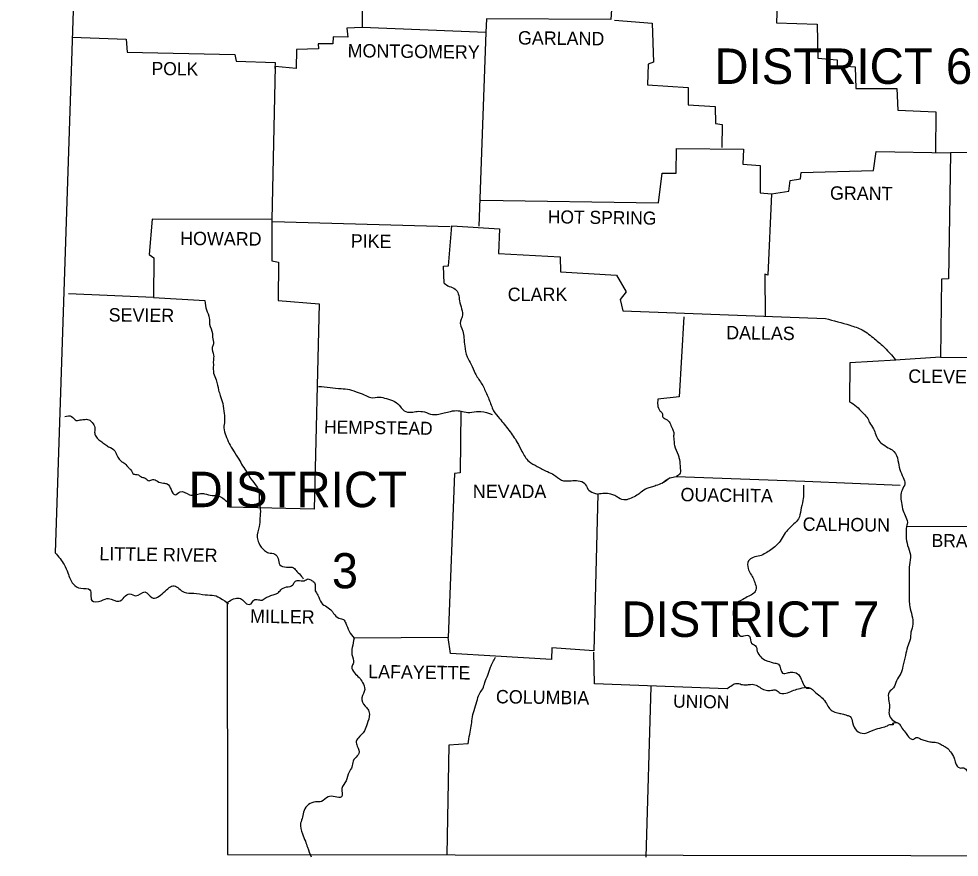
# Model space of a CAD drawing. Extents: x -17668 to 16999, y -17303 to 5867.
# Drawn here: x 1332 to 2998, y 2895 to 4379 of the extents above; entities that cross this region are included whole.
import ezdxf

# ---------------------------------------------------------------- set-up
doc = ezdxf.new("R2010")
doc.units = 0
for name, color, linetype in [('1', 7, 'Continuous'), ('2', 7, 'Continuous'), ('3', 7, 'Continuous')]:
    doc.layers.add(name, color=color, linetype=linetype)

msp = doc.modelspace()

# ---------------------------------------------------------------- linework, layer by layer
at = {"layer": '1'}
for points in [[(1332.2, 5841.4), (1446.1, 4926.7), (1396.6, 3433.6)], [(1941.4, 4685.1), (1940.3, 4363.2), (1912.8, 4362.6), (1915, 4346.1), (1888.6, 4346.7), (1888, 4334.6), (1862.2, 4334.6), (1862.7, 4325.8), (1824.2, 4324.7), (1823.6, 4291.1), (1786.2, 4294.4), (1780.2, 4023.6), (1568.3, 4024.2), (1563.3, 3961.4), (1571, 3955.9), (1570.5, 3885.5), (1420.2, 3892.1)], [(2565.5, 4443), (2385.5, 4448.5), (2380.6, 4377.5), (2160.4, 4378.6), (2159.3, 4354.9)], [(2614.5, 4444.6), (2676.1, 4440.8), (2673.9, 4372), (2746, 4369.2), (2747.1, 4309.2), (2781.2, 4306.5), (2781.2, 4296), (2813.2, 4293.8), (2814.3, 4255.3), (2886.9, 4255.3), (2889.1, 4217.3), (2956.3, 4214), (2955.7, 4142.5)], [(2387.2, 4376.4), (2453.8, 4371.4), (2456, 4302.1), (2446.6, 4298.8), (2445.5, 4261.9), (2517.6, 4257), (2517.6, 4226.7), (2565.5, 4223.9), (2566.1, 4193.7), (2577.6, 4192), (2577.1, 4151.3)], [(2159.3, 4354.9), (1940.3, 4363.2)], [(2159.3, 4354.9), (2146.7, 4012.1)], [(1426.8, 4346.1), (1522, 4342.8), (1524.2, 4319.7), (1714.7, 4315.8), (1716.9, 4303.7), (1786.2, 4301.5), (1785.7, 4291.1)], [(3612.3, 4205.8), (3404.2, 4211.3), (3403.1, 4143.6), (2982.1, 4141.9)], [(2150.5, 4057.7), (2465.3, 4053.3), (2471.4, 4105.6), (2496.2, 4105.6), (2496.7, 4149.6), (2615.6, 4148), (2614.5, 4121.6), (2645.3, 4119.4), (2645.3, 4070.9), (2665.1, 4069.3)], [(2665.1, 4069.3), (2695.9, 4073.7), (2698.1, 4092.4), (2716.3, 4095.7), (2717.4, 4106.7), (2845.6, 4110.6), (2850.6, 4144.1), (2982.1, 4141.9)], [(2982.1, 4140.8), (2978.8, 3918.5), (2966.2, 3917.9), (2964.5, 3779.8)], [(2665.1, 4069.3), (2658.5, 3925.1), (2653.6, 3926.7), (2654.1, 3851.9)], [(1780.2, 4023.6), (1780.2, 3950.4), (1792.3, 3948.2), (1791.2, 3880), (1863.8, 3874.5), (1855, 3510.7), (1705.3, 3514.5)], [(1781.3, 4019.8), (2096.1, 4011.5)], [(2085.6, 3910.8), (2084.5, 3941.1), (2093.3, 3941.6), (2098.8, 4012.6), (2183.6, 4007.1), (2181.4, 3963.6), (2290.9, 3957.6), (2291.4, 3931.2), (2390.5, 3925.1), (2407.6, 3895.4), (2397.1, 3882.2), (2402.1, 3861.8), (2760.9, 3848.6)], [(1570.5, 3885.5), (1661.8, 3880)], [(2509.9, 3851.4), (2501.7, 3709.9), (2463.7, 3705.5)], [(2885.3, 3774.9), (2803.8, 3769.9), (2803.3, 3701.1)], [(2964.5, 3779.8), (2884.2, 3774.9)], [(2964.5, 3779.8), (3159.3, 3778.7)], [(2114.8, 3684.6), (2113.7, 3575.1), (2103.8, 3574), (2092.8, 3283.9)], [(2496.2, 3568.5), (2724, 3560.2), (2893, 3553.6)], [(2357.5, 3537.6), (2350.3, 3260.3), (2276, 3265.2), (2275.5, 3244.9), (2176.4, 3250.9)], [(2904, 3480.4), (3152.7, 3481)], [(1700.9, 3345), (1702, 2899.8), (3719, 2896.5)], [(2176.4, 3250.9), (2096.6, 3255.3), (2092.8, 3283.9), (1926, 3282.3)], [(2586.4, 3193.1), (2351.4, 3201.9), (2350.3, 3257.5)], [(2451.6, 3197), (2442.8, 2894.8)], [(2128, 3095.2), (2093.9, 3093), (2090, 2899.2)]]:
    msp.add_lwpolyline(points, dxfattribs=at)
for points in [[(2085.6, 3910.8), (2094.4, 3905.3), (2104.9, 3900.3), (2110.4, 3892.1), (2112.6, 3879.4), (2116.4, 3865.7), (2117.5, 3851.4), (2114.2, 3843.6), (2118.6, 3826), (2120.3, 3813.9), (2121.9, 3799.6), (2126.3, 3780.4), (2133.5, 3767.1), (2140.1, 3751.2), (2151.1, 3734.1), (2160.4, 3715.4), (2164.8, 3705.5), (2173.1, 3685.1), (2183.6, 3671.4), (2200.1, 3650.5), (2214.9, 3629), (2223.2, 3613), (2235.8, 3595.4), (2250.2, 3586.6), (2268.3, 3577.3), (2279.9, 3571.8), (2293.1, 3562.4), (2310.1, 3561.3), (2322.8, 3561.3), (2334.4, 3556.4), (2339.9, 3546.5), (2349.8, 3539.9), (2357.5, 3537.6)], [(1661.8, 3880), (1664.6, 3863.5), (1669.5, 3849.1), (1670.1, 3838.1), (1675, 3821.6), (1675, 3815.6), (1676.7, 3803.5), (1674.5, 3796.9), (1677.2, 3783.7), (1676.7, 3773.8), (1676.7, 3765.5), (1677.2, 3751.7), (1681.6, 3739.6), (1686, 3721.5), (1688.8, 3712.1), (1693.2, 3697.8), (1695.9, 3680.2), (1696.5, 3667), (1695.4, 3654.9), (1698.7, 3641.1), (1704.8, 3627.4), (1712.5, 3614.1), (1721.8, 3599.3), (1728.4, 3587.7), (1736.7, 3575.1), (1743.3, 3564.6), (1753.2, 3551.4), (1757.6, 3540.4), (1757.6, 3525), (1759.8, 3510.7), (1759.2, 3494.7), (1758.1, 3480.4), (1754.3, 3460.6), (1757, 3451.2), (1767.5, 3437.5), (1774.1, 3433.6), (1785.7, 3431.4), (1791.2, 3423.7), (1794.5, 3412.2), (1806, 3408.3), (1818.7, 3407.2), (1824.7, 3400.6), (1833, 3391.8), (1835.7, 3387.4)], [(2760.9, 3848.6), (2803.8, 3836.5), (2825.8, 3828.2), (2847.8, 3812.3), (2866, 3796.3), (2884.2, 3776)], [(1862.7, 3728.1), (1883.6, 3726.4), (1902.9, 3724.2), (1917.7, 3722.6), (1933.2, 3717.1), (1946.9, 3712.1), (1955.7, 3708.3), (1970.6, 3709.4), (1983.2, 3706.6), (1997.5, 3701.7), (2008, 3692.3), (2014.6, 3685.1), (2027.3, 3682.4), (2037.7, 3684), (2050.4, 3682.9), (2064.7, 3678.5), (2076.2, 3679.1), (2085.6, 3681.3), (2096.6, 3684), (2110.4, 3685.1), (2120.8, 3682.9), (2134.6, 3682.4), (2150.5, 3684), (2170.4, 3678.5)], [(2463.7, 3705.5), (2463.7, 3695), (2467.5, 3685.1), (2471.4, 3680.7), (2473, 3673.6), (2478, 3670.3), (2485.2, 3663.7), (2489, 3654.3), (2491.8, 3648.3), (2491.8, 3640.6), (2492.3, 3632.9), (2493.4, 3623.5), (2500, 3607), (2501.7, 3600.4), (2502.8, 3594.9), (2503.3, 3585.5), (2503.3, 3574.5), (2496.2, 3568.5)], [(2803.3, 3701.1), (2815.9, 3692.8), (2826.4, 3681.8), (2834.1, 3673.6), (2839, 3664.2), (2845.6, 3653.2), (2855, 3632.3), (2863.2, 3625.2), (2874.8, 3618), (2882, 3613), (2889.1, 3597.1), (2892.4, 3581.1), (2898.5, 3566.8), (2901.2, 3555.8), (2896.3, 3544.8), (2895.2, 3522.8), (2898.5, 3507.9), (2902.9, 3496.9), (2905.6, 3484.3), (2904, 3480.4)], [(1413.6, 3674.7), (1425.7, 3675.2), (1434, 3668.1), (1438.9, 3668.6), (1447.7, 3669.7), (1456, 3669.2), (1462, 3664.2), (1467, 3655.4), (1466.5, 3647.2), (1467, 3643.9), (1470.9, 3636.7), (1477.5, 3631.2), (1484.6, 3625.7), (1491.2, 3621.3), (1502.2, 3614.1), (1503.3, 3611.9), (1507.7, 3603.1), (1513.2, 3596), (1519.8, 3591.6), (1527, 3583.9), (1530.3, 3580.6), (1535.8, 3572.9), (1541.8, 3572.3), (1550.1, 3567.4), (1556.2, 3565.7), (1562.8, 3561.3), (1569.4, 3563.5), (1577.6, 3560.2), (1588.6, 3556.9), (1594.7, 3555.8), (1601.8, 3545.4), (1609, 3536.5), (1617.8, 3541.5), (1634.3, 3536.5), (1644.8, 3536), (1654.1, 3538.7), (1661.3, 3538.2), (1674.5, 3534.9), (1682.7, 3534.9), (1691.5, 3531.6), (1699.8, 3525), (1705.3, 3517.8), (1705.3, 3514.5)], [(2485.7, 3566.3), (2471.4, 3556.9), (2460.4, 3552.5), (2452.1, 3549.8), (2444.4, 3547.6), (2434.5, 3541), (2426.8, 3535.4), (2416.4, 3530.5), (2406.5, 3527.2), (2394.3, 3531), (2387.7, 3534.9), (2380.6, 3537.6), (2357.5, 3537.6)], [(2471.4, 3556.9), (2485.7, 3566.3), (2496.2, 3568.5)], [(2721.8, 3553.6), (2720.7, 3526.1), (2716.9, 3509), (2713, 3493.6), (2704.7, 3484.8), (2695.9, 3476), (2687.7, 3466.1), (2680.5, 3454), (2673.4, 3446.3), (2664, 3438.6), (2654.7, 3433.1), (2644.2, 3428.1), (2632.7, 3425.4), (2624.4, 3419.3), (2623.8, 3406.1), (2633.2, 3387.4), (2636.5, 3378.6), (2637.6, 3368.1), (2633.8, 3362.1), (2624.9, 3357.1), (2614.5, 3351.1), (2605.1, 3345.6), (2598.5, 3336.2), (2597.4, 3323.6), (2601.8, 3308.7), (2603.5, 3299.9), (2610.6, 3286.1), (2616.1, 3286.7), (2626, 3286.1), (2627.1, 3283.4), (2627.7, 3280.6), (2629.9, 3273.5), (2638.2, 3267.4), (2639.3, 3261.9), (2644.2, 3251.5), (2652.5, 3244.3), (2658.5, 3242.1), (2671.2, 3238.3), (2677.8, 3236.6), (2684.9, 3220.6), (2693.7, 3221.2), (2700.3, 3222.3), (2711.4, 3219.5), (2716.3, 3212.9), (2721.3, 3201.9), (2727.9, 3194.2), (2732.3, 3194.2)], [(2904, 3480.4), (2906.2, 3446.3), (2911.1, 3429.8), (2909.5, 3412.2), (2908.9, 3395.1), (2908.9, 3379.7), (2908.9, 3364.8), (2908.9, 3349.4), (2910, 3338.4), (2913.9, 3322.5), (2915.5, 3307.6), (2912.2, 3293.3), (2910.6, 3280.1), (2906.2, 3266.9), (2902.3, 3252), (2897.9, 3232.8), (2894.1, 3220.1), (2886.4, 3206.9), (2881.4, 3194.8), (2873.7, 3187.1), (2872.6, 3173.9), (2874.3, 3161.8), (2873.2, 3150.7), (2877, 3140.3), (2886.9, 3133.1)], [(1396.6, 3433.6), (1412.5, 3412.7), (1419.1, 3397.9), (1428.5, 3378.6), (1442.2, 3370.9), (1458.2, 3368.1), (1461.5, 3349.4), (1478, 3348.9), (1491.2, 3352.7), (1509.4, 3347.8), (1528.6, 3361), (1539.6, 3357.7), (1555.6, 3364.3), (1567.7, 3354.4), (1588.6, 3363.2), (1607.3, 3375.3), (1625, 3363.7), (1642, 3362.1), (1662.4, 3359.3), (1678.3, 3358.2), (1692.6, 3351.1), (1703.1, 3343.9), (1700.9, 3345)], [(1700.9, 3345), (1720.2, 3353.3), (1728.4, 3350.5), (1735.6, 3343.4), (1743.8, 3343.4), (1748.2, 3350), (1756.5, 3350.5), (1763.1, 3350), (1770.2, 3354.4), (1776.3, 3357.1), (1784.6, 3359.9), (1790.6, 3362.1), (1796.1, 3368.1), (1806, 3373.1), (1817.6, 3376.9), (1820.9, 3382.4), (1826.4, 3384.7), (1837.4, 3384.1), (1844.5, 3387.4), (1850.6, 3384.7), (1856.1, 3380.8), (1857.2, 3366.5), (1861.6, 3358.8), (1868.2, 3345), (1877.6, 3337.9), (1886.4, 3330.7), (1889.7, 3326.3), (1899, 3318.1), (1907.3, 3315.3), (1911.1, 3309.3), (1917.2, 3294.9), (1926, 3282.3)], [(1926, 3282.3), (1922.7, 3266.3), (1922.1, 3253.7), (1924.9, 3238.8), (1922.1, 3231.7), (1926.5, 3221.2), (1934.8, 3212.9), (1940.9, 3204.1), (1944.7, 3191.5), (1939.8, 3177.2), (1945.3, 3162.3), (1950.2, 3156.8), (1953, 3148), (1949.1, 3130.9), (1944.2, 3118.3), (1933.2, 3105.6), (1929.8, 3099.6), (1931.5, 3091.3), (1934.3, 3078.1), (1931.5, 3074.3), (1924.3, 3064.9), (1922.1, 3054.4), (1917.2, 3045.6), (1911.7, 3029.7), (1904.5, 3016.5), (1903.4, 3001.6), (1892.4, 3001.6), (1879.8, 3001.6), (1868.2, 2993.3), (1857.8, 2992.8), (1845.1, 2987.8), (1837.4, 2977.4), (1834.6, 2965.8), (1831.3, 2954.8), (1834.6, 2936.1), (1839.6, 2922.9), (1843.4, 2912.4), (1850, 2895.4)], [(2128, 3095.2), (2130.7, 3112.8), (2133.5, 3126.5), (2135.1, 3139.7), (2138.4, 3154.6), (2143.4, 3170.6), (2147.8, 3183.8), (2153.8, 3193.1), (2157.7, 3204.1), (2162.6, 3217.3), (2167.6, 3231.1), (2176.4, 3248.7)], [(2586.4, 3193.1), (2595.2, 3199.2), (2603.5, 3202.5), (2611.7, 3200.8), (2620.5, 3199.7), (2628.2, 3200.8), (2638.2, 3199.2), (2646.4, 3194.2), (2655.8, 3190.4), (2665.1, 3190.4), (2673.4, 3190.4), (2680.5, 3185.4), (2693.7, 3186), (2704.7, 3190.4), (2715.8, 3193.7), (2730.6, 3195.3), (2743.8, 3186), (2753.2, 3178.3), (2760.9, 3169.5), (2766.4, 3159.6), (2772.4, 3154.1), (2782.3, 3150.2), (2790.1, 3148.5), (2799.4, 3145.8), (2804.4, 3143.6), (2808.8, 3133.1), (2815.9, 3118.8), (2829.7, 3113.9), (2846.7, 3120.5), (2860.5, 3124.3), (2870.4, 3127.6), (2876.5, 3129.8), (2882, 3130.4), (2880.3, 3131.5), (2886.9, 3133.1), (2893, 3128.7), (2896.8, 3122.7), (2903.4, 3113.9), (2909.5, 3106.2), (2915.5, 3103.4), (2921.6, 3106.7), (2929.8, 3104), (2937, 3101.2), (2945.3, 3099), (2952.4, 3098.5), (2961.8, 3096.3), (2968.9, 3092.4), (2975.5, 3088.6), (2982.1, 3081.4), (2988.7, 3070.4), (2990.9, 3061.6), (2998.6, 3052.8), (3005.8, 3052.8), (3016.2, 3038.5), (3020.1, 3033), (3028.4, 3023.1), (3034.4, 3023.1), (3046, 3020.9)]]:
    msp.add_spline(points, degree=3, dxfattribs=at)

# ---------------------------------------------------------------- texts
at = {"layer": '2'}
for s, height, rotation, p in [('GARLAND', 23.67, 359.3658, (2216, 4333.5)), ('MONTGOMERY', 23.67, 359.2944, (1914.4, 4310.9)), ('POLK', 23.11, 359.2152, (1567.2, 4279.5)), ('GRANT', 23.67, 359.4032, (2768.6, 4058.8)), ('HOT SPRING', 23.11, 359.2216, (2268.9, 4017)), ('HOWARD', 23.67, 359.5145, (1617.8, 3978.5)), ('PIKE', 23.66, 359.0452, (1919.9, 3974.1)), ('SEVIER', 23.67, 359.4271, (1491.2, 3843.1)), ('DALLAS', 23.66, 359.2462, (2584.8, 3811.7)), ('CLEVELAND', 23.67, 359.3377, (2907.3, 3734.7)), ('HEMPSTEAD', 23.11, 359.1885, (1872.6, 3645)), ('OUACHITA', 23.67, 359.2043, (2503.9, 3525)), ('CALHOUN', 23.67, 359.3634, (2720.2, 3472.7)), ('BRADLEY', 23.11, 359.1449, (2948.6, 3444.1)), ('LITTLE RIVER', 23.666, 359.1697, (1474.7, 3420.4)), ('MILLER', 23.66, 359.1319, (1741.6, 3309.8)), ('LAFAYETTE', 23.66, 359.1839, (1950.8, 3211.8)), ('COLUMBIA', 23.66, 359.2125, (2177, 3167.3)), ('UNION', 23.11, 358.9584, (2490.7, 3159.6))]:
    msp.add_text(s, height=height, rotation=rotation, dxfattribs=at).set_placement(p)
for s, p in [('CLARK', (2198, 3879.3)), ('NEVADA', (2136.2, 3530.5))]:
    msp.add_text(s, height=23.67, dxfattribs=at).set_placement(p)
at = {"layer": '3'}
for s, height, p in [('DISTRICT 6', 62.74, (2563.9, 4263.6)), ('DISTRICT', 62.74, (1632.8, 3514.4)), ('3', 62.2, (1886.6, 3370.8)), ('DISTRICT 7', 62.74, (2399.2, 3284.8))]:
    msp.add_text(s, height=height, dxfattribs=at).set_placement(p)

doc.saveas('drawing.dxf')
